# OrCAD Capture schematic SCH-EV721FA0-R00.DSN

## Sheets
1 Block Diagram: title: G2; rev: 1.0; note: Ver1.0
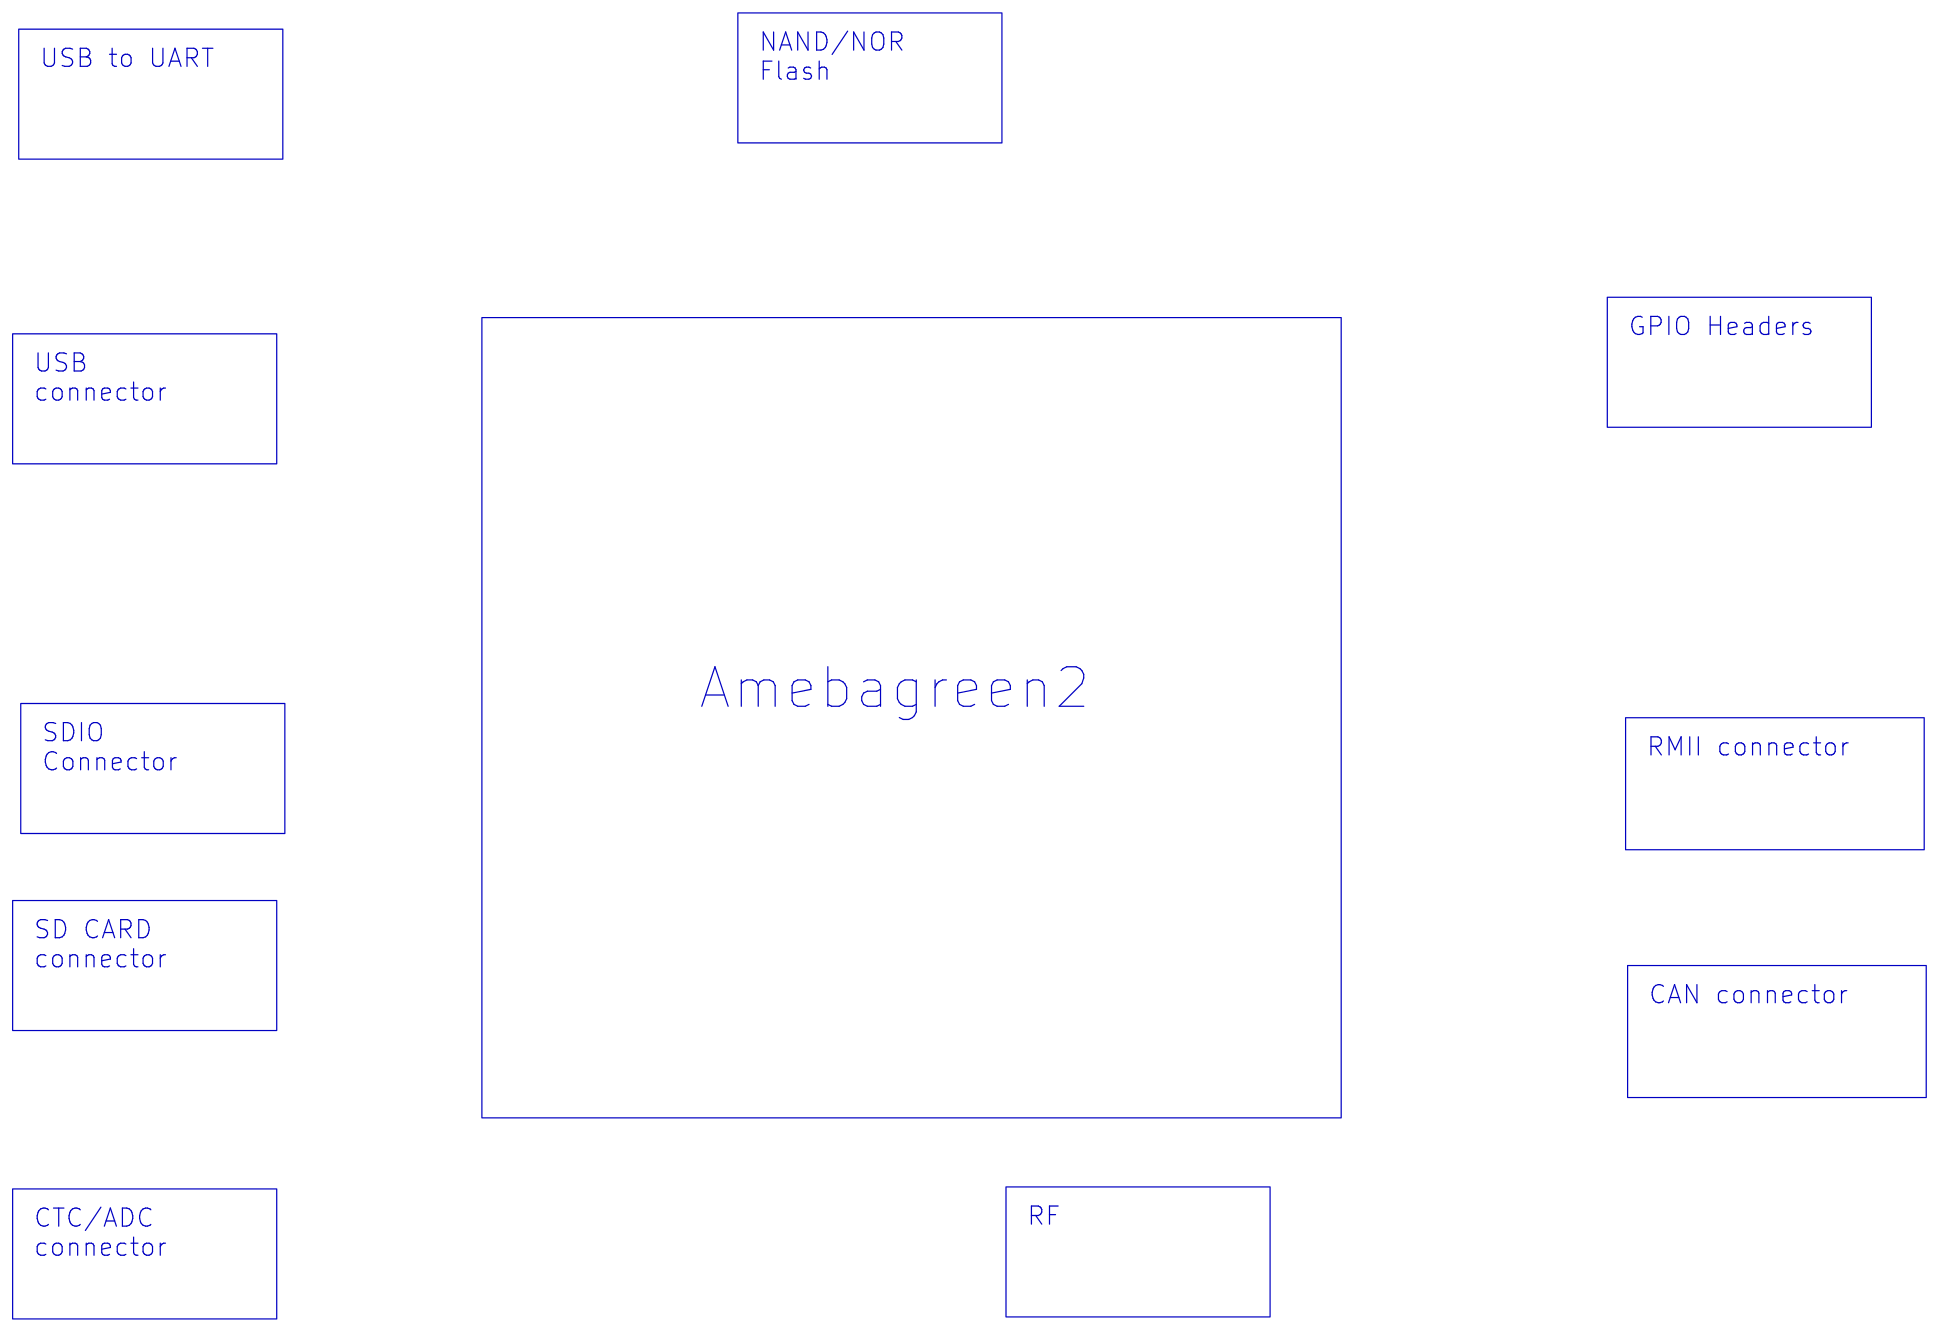
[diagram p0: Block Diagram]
2 Power Tree
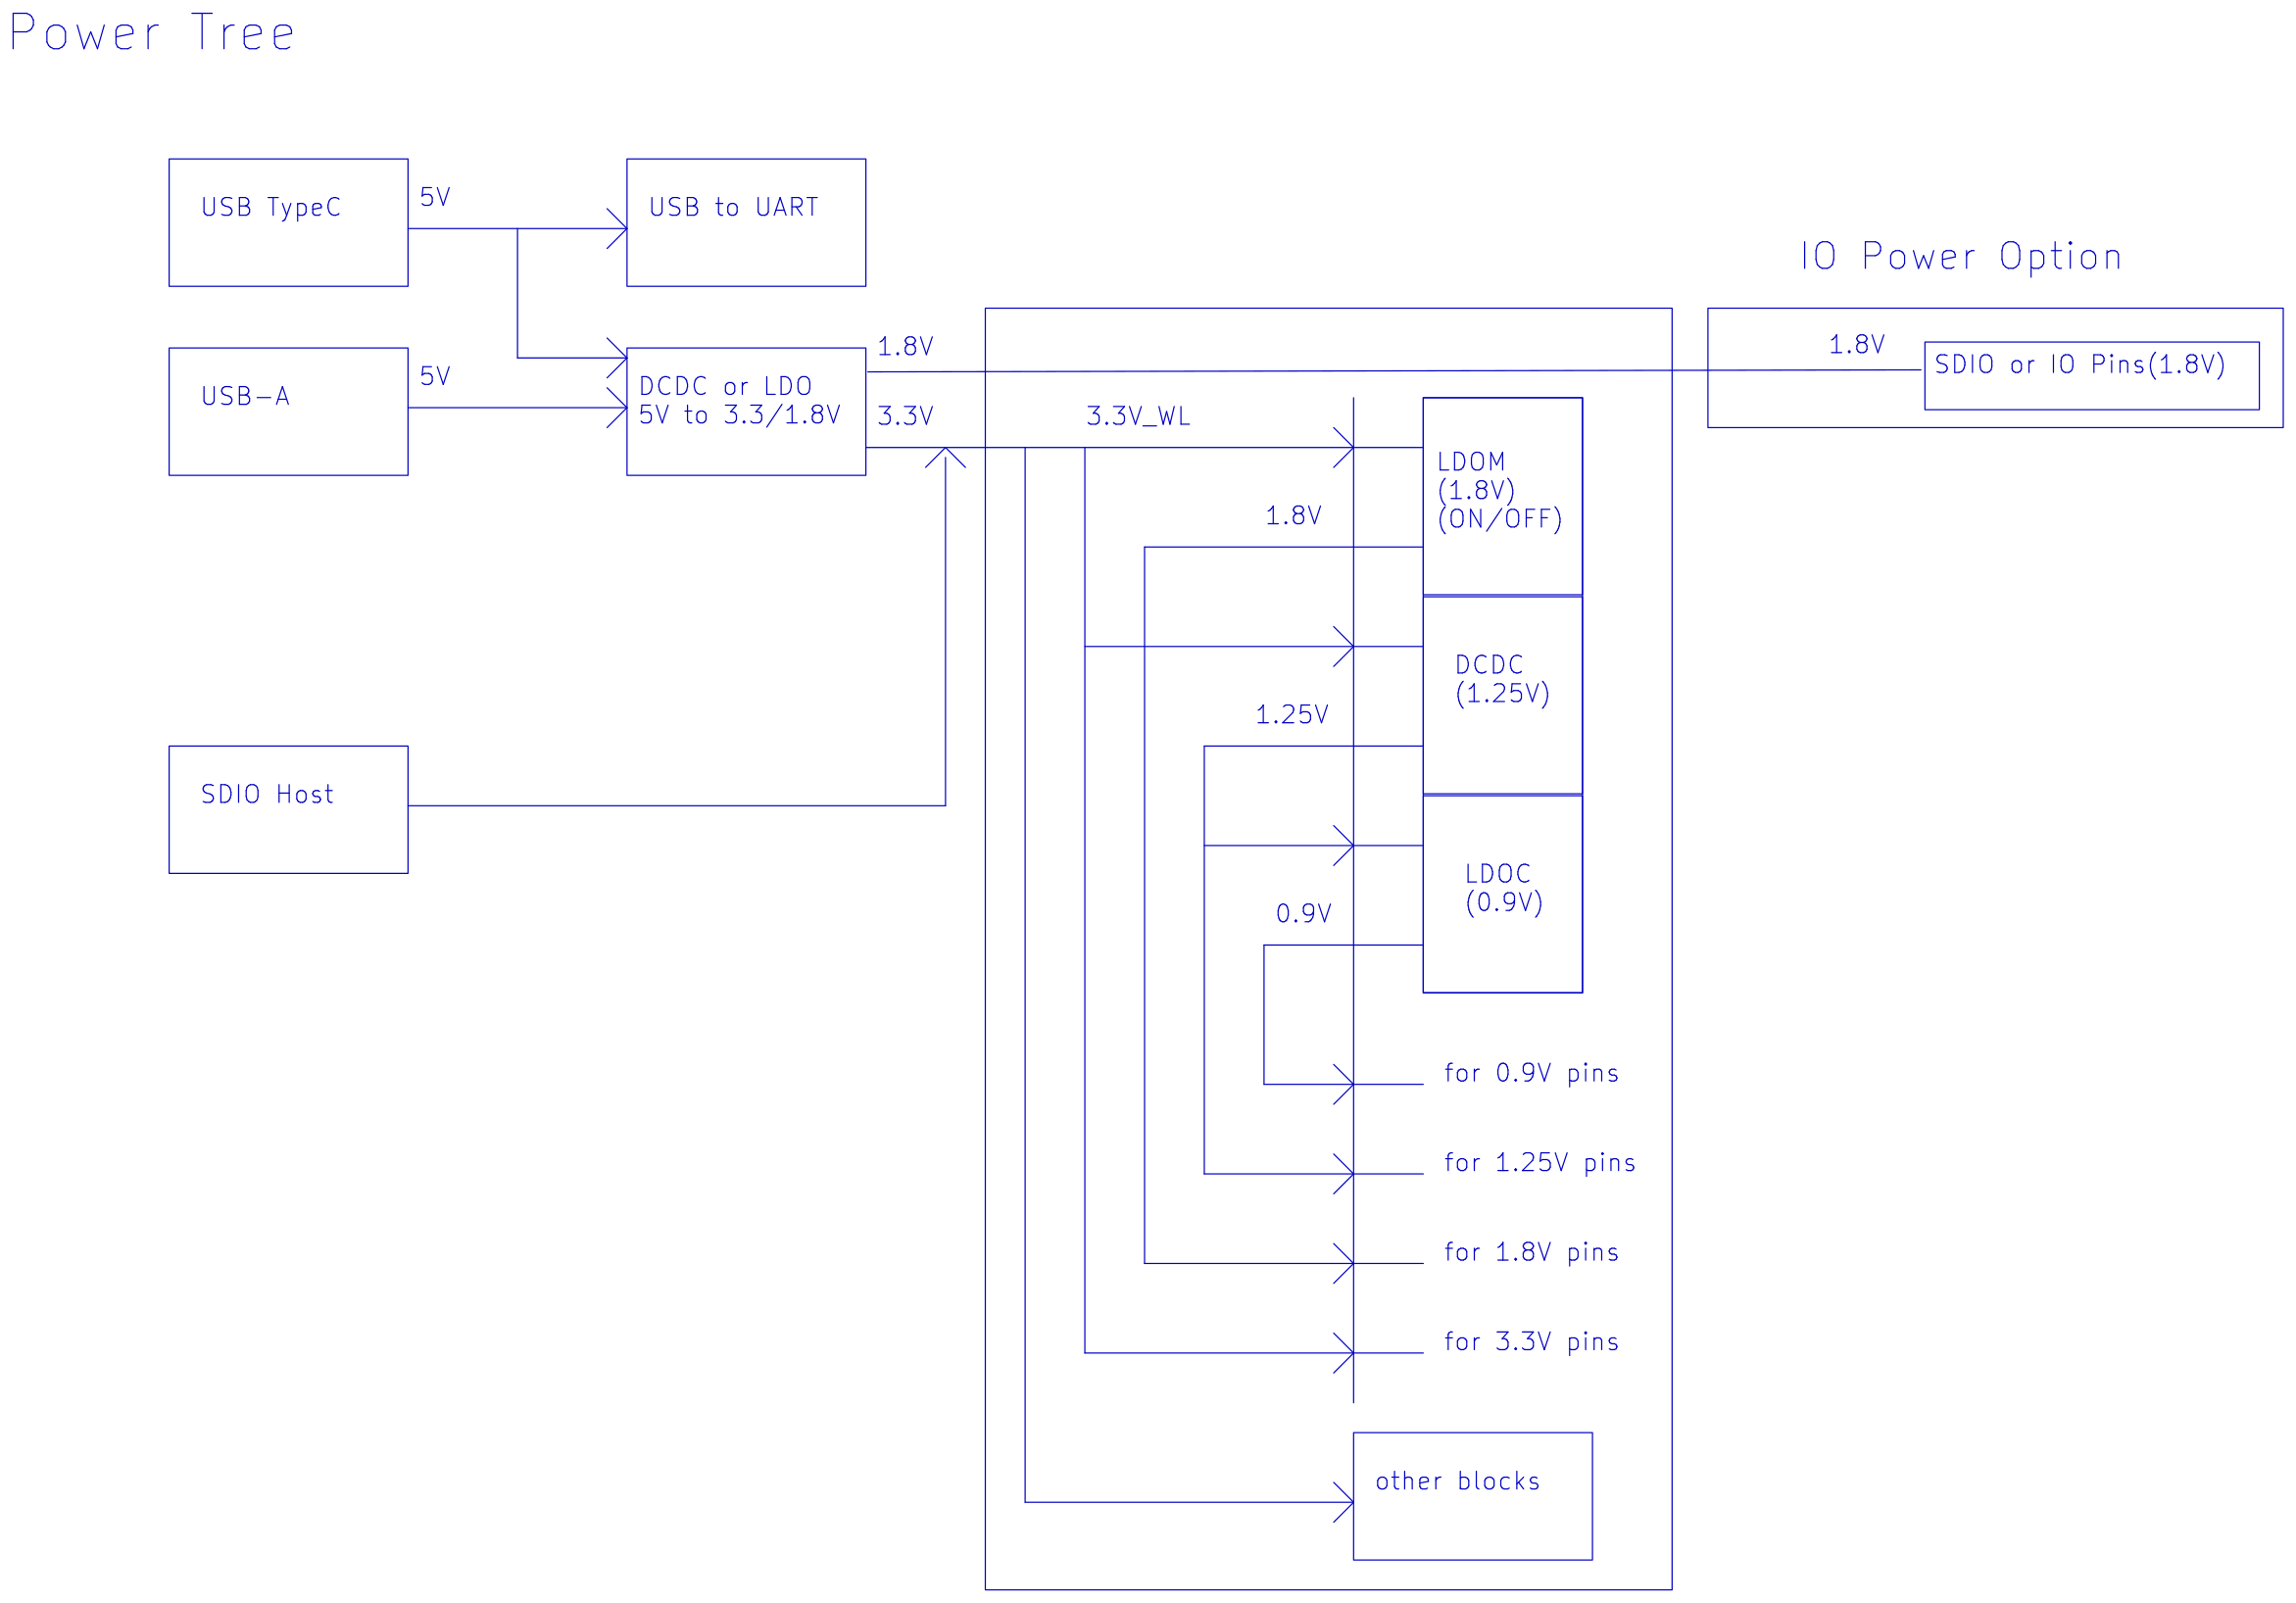
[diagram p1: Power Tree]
3 USB&POWER: size C
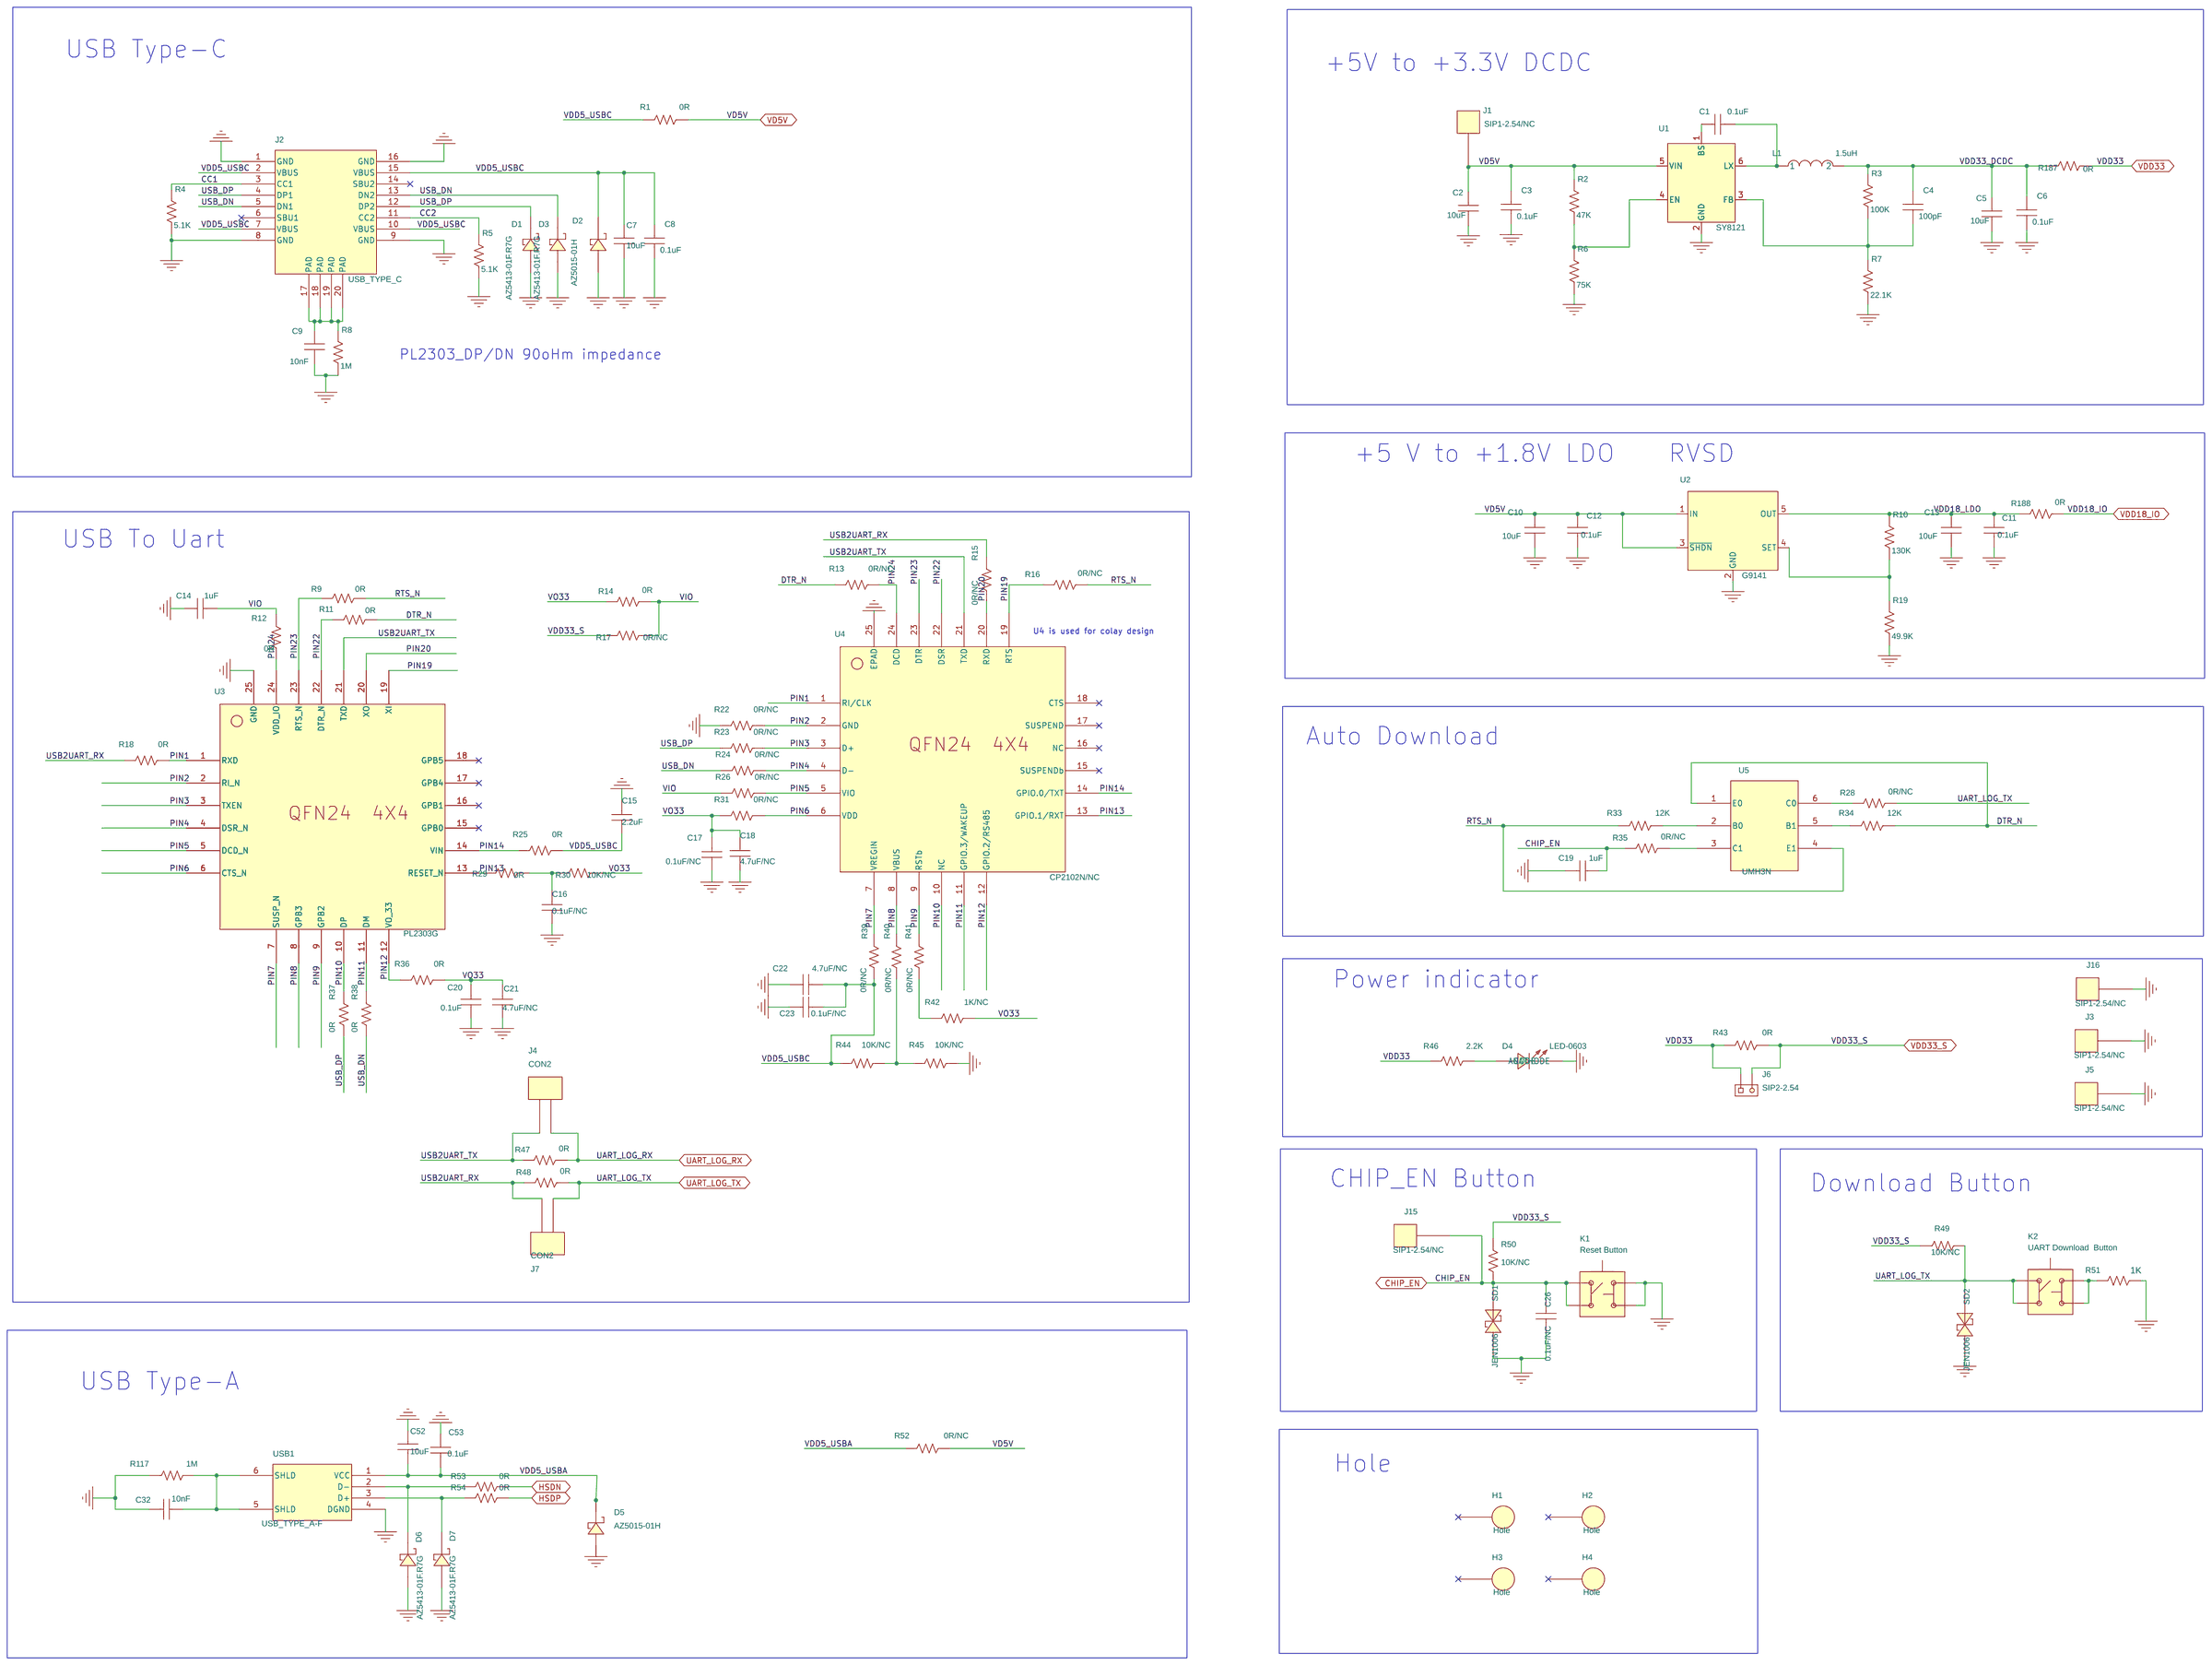
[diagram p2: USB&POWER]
4 Module: size C
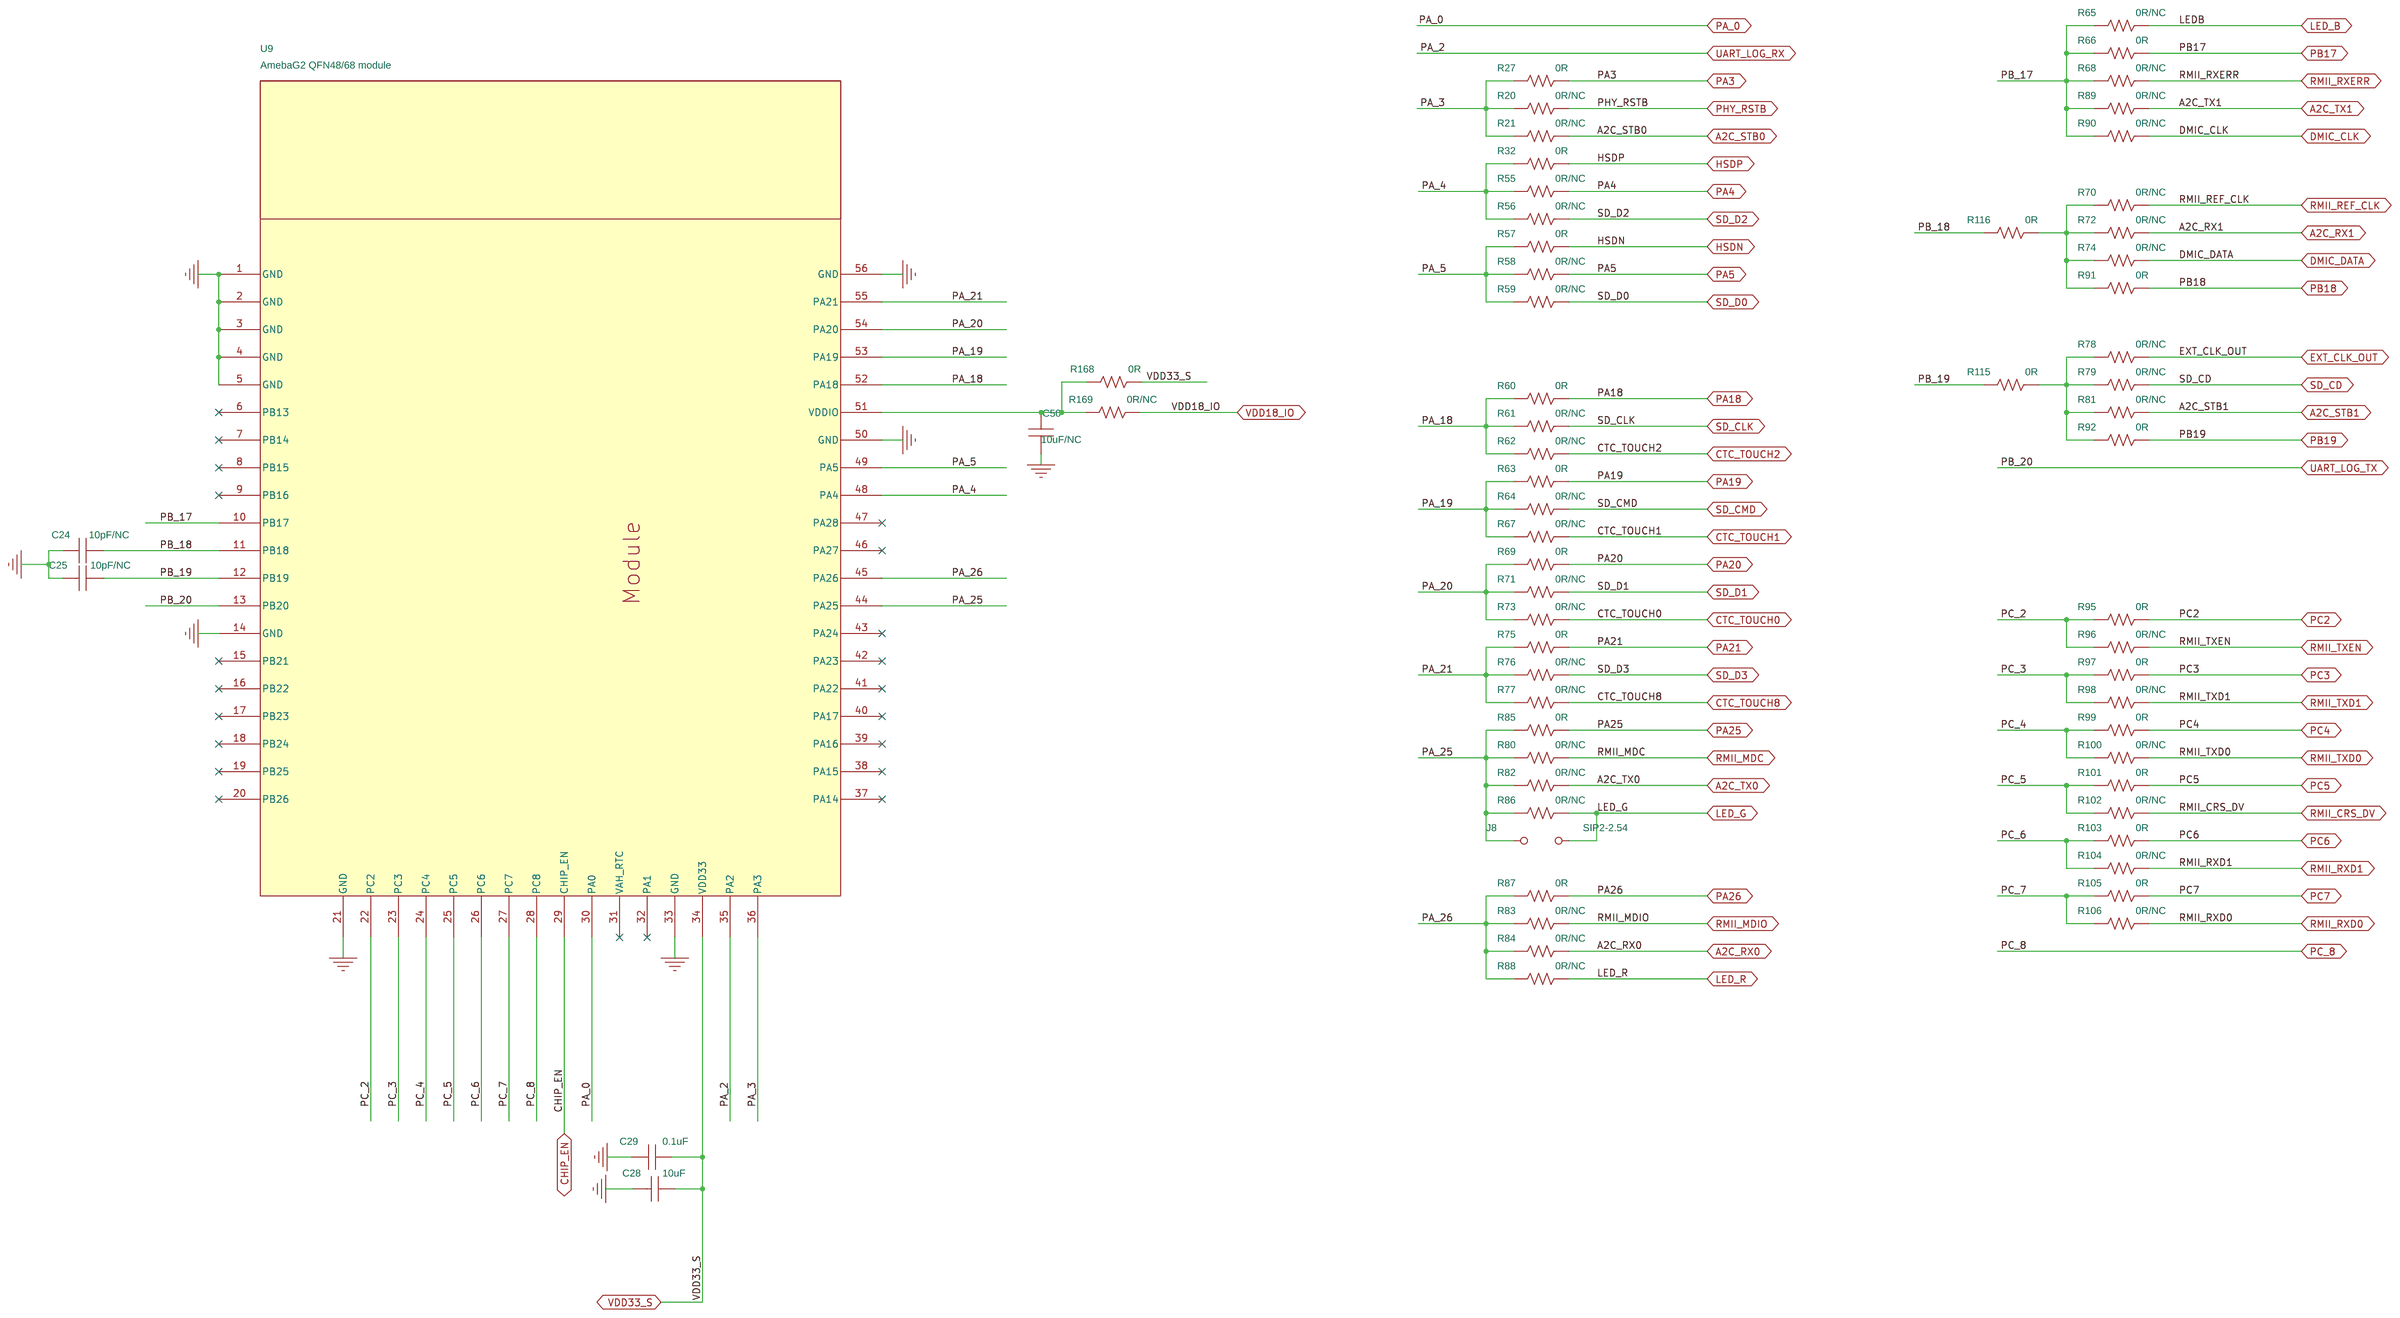
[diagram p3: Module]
5 Function: size C
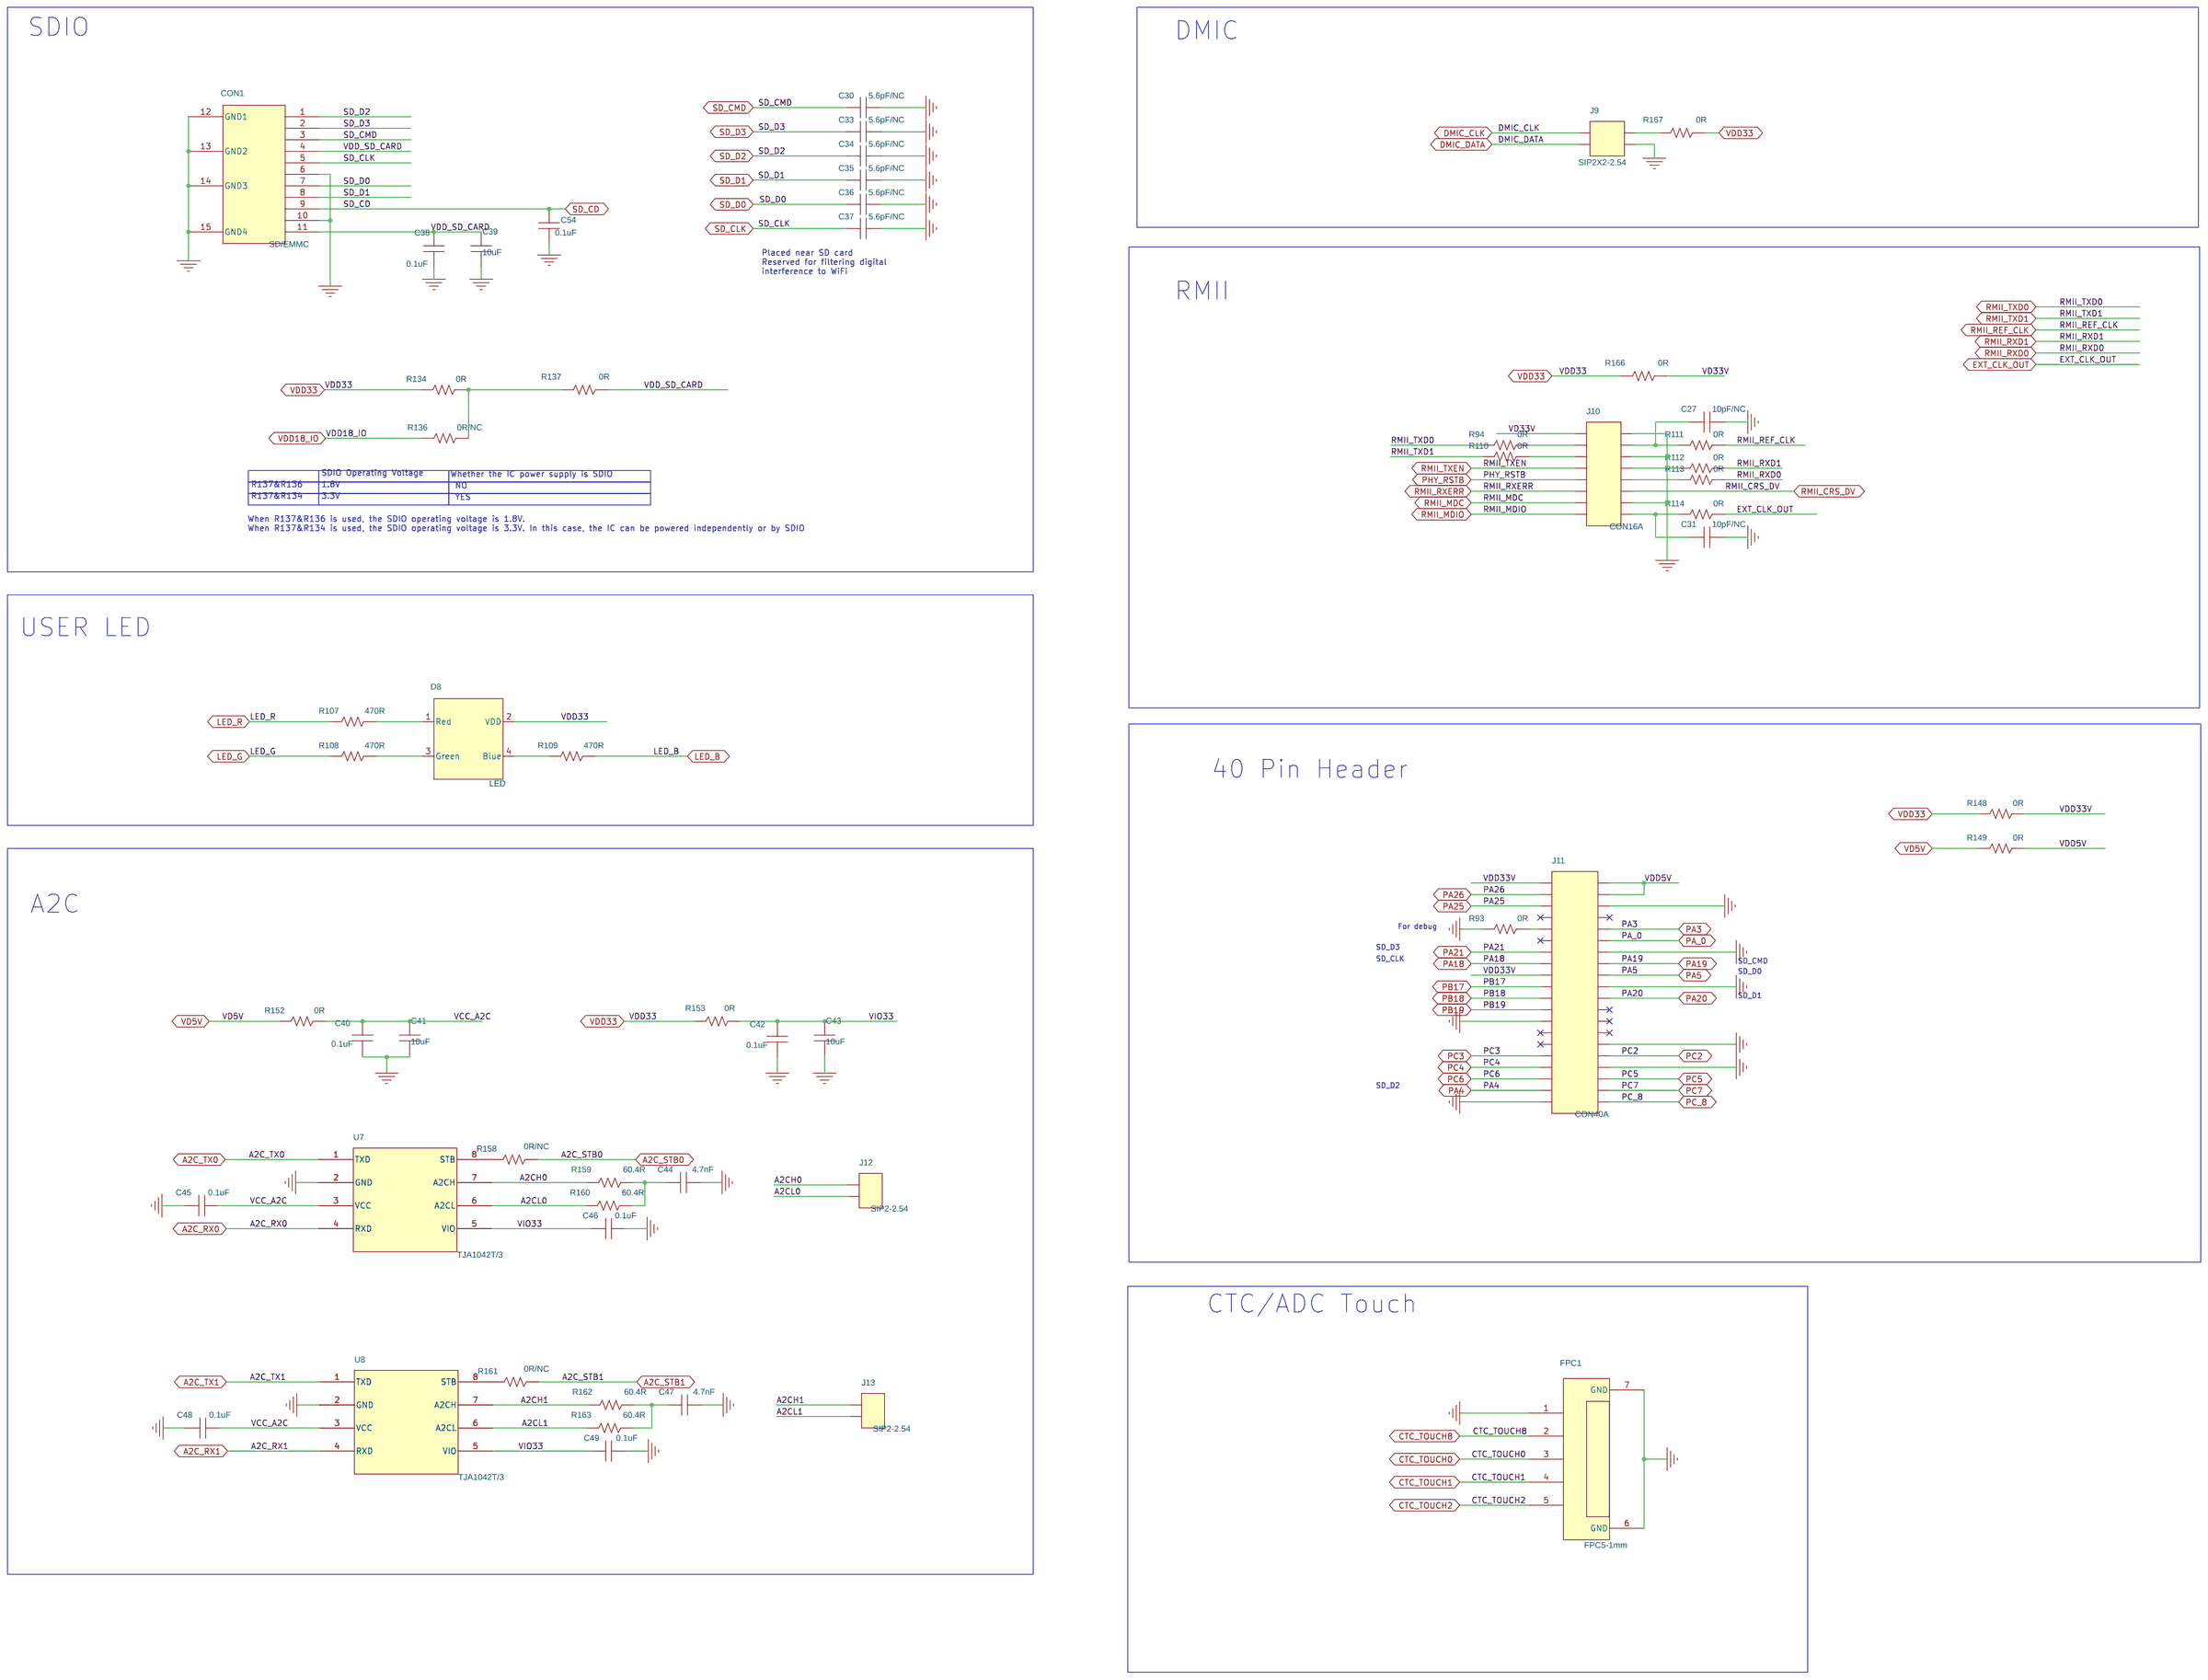
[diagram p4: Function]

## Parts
sheet Function
C27  10pF/NC  [C0402]
C30  5.6pF/NC  [C0402]
C31  10pF/NC  [C0402]
C33  5.6pF/NC  [C0402]
C34  5.6pF/NC  [C0402]
C35  5.6pF/NC  [C0402]
C36  5.6pF/NC  [C0402]
C37  5.6pF/NC  [C0402]
C38  0.1uF  [C0402]
C39  10uF  [C0603]
C40  0.1uF  [C0402]
C41  10uF  [C0603]
C42  0.1uF  [C0402]
C43  10uF  [C0603]
C44  4.7nF  [C0402]
C45  0.1uF  [C0402]
C46  0.1uF  [C0402]
C47  4.7nF  [C0402]
C48  0.1uF  [C0402]
C49  0.1uF  [C0402]
C54  0.1uF  [C0402]
CON1  SD/EMMC  [SD_CARD15]
D8  LED  [LED-3528]
FPC1  FPC5-1mm  [FPC5-1]
J9  SIP2X2-2.54  [SIP2X2-2.54]
J10  CON16A  [SIP8X2-2.54]
J11  CON40A  [SIP20X2-2.54]
J12  SIP2-2.54  [SIP2-2.54]
J13  SIP2-2.54  [SIP2-2.54]
R93  0R  [R0402]
R94  0R  [R0402]
R107  470R  [R0402]
R108  470R  [R0402]
R109  470R  [R0402]
R110  0R  [R0402]
R111  0R  [R0402]
R112  0R  [R0402]
R113  0R  [R0402]
R114  0R  [R0402]
R134  0R  [R0402]
R136  0R/NC  [R0402]
R137  0R  [R0805]
R148  0R  [R0805]
R149  0R  [R0805]
R152  0R  [R0402]
R153  0R  [R0402]
R158  0R/NC  [R0402]
R159  60.4R  [R0402]
R160  60.4R  [R0402]
R161  0R/NC  [R0402]
R162  60.4R  [R0402]
R163  60.4R  [R0402]
R166  0R  [R0402]
R167  0R  [R0402]
U7  TJA1042T/3  [SO8-150-4.9X3.9]
U8  TJA1042T/3  [SO8-150-4.9X3.9]
sheet Module
C24  10pF/NC  [C0402]
C25  10pF/NC  [C0402]
C28  10uF  [C0603]
C29  0.1uF  [C0603]
C50  10uF/NC  [C0402]
J8  SIP2-2.54  [SIP2-2.54]
R20  0R/NC  [R0402]
R21  0R/NC  [R0402]
R27  0R  [R0402]
R32  0R  [R0402]
R55  0R/NC  [R0402]
R56  0R/NC  [R0402]
R57  0R  [R0402]
R58  0R/NC  [R0402]
R59  0R/NC  [R0402]
R60  0R  [R0402]
R61  0R/NC  [R0402]
R62  0R/NC  [R0402]
R63  0R  [R0402]
R64  0R/NC  [R0402]
R65  0R/NC  [R0402]
R66  0R  [R0402]
R67  0R/NC  [R0402]
R68  0R/NC  [R0402]
R69  0R  [R0402]
R70  0R/NC  [R0402]
R71  0R/NC  [R0402]
R72  0R/NC  [R0402]
R73  0R/NC  [R0402]
R74  0R/NC  [R0402]
R75  0R  [R0402]
R76  0R/NC  [R0402]
R77  0R/NC  [R0402]
R78  0R/NC  [R0402]
R79  0R/NC  [R0402]
R80  0R/NC  [R0402]
R81  0R/NC  [R0402]
R82  0R/NC  [R0402]
R83  0R/NC  [R0402]
R84  0R/NC  [R0402]
R85  0R  [R0402]
R86  0R/NC  [R0402]
R87  0R  [R0402]
R88  0R/NC  [R0402]
R89  0R/NC  [R0402]
R90  0R/NC  [R0402]
R91  0R  [R0402]
R92  0R  [R0402]
R95  0R  [R0402]
R96  0R/NC  [R0402]
R97  0R  [R0402]
R98  0R/NC  [R0402]
R99  0R  [R0402]
R100  0R/NC  [R0402]
R101  0R  [R0402]
R102  0R/NC  [R0402]
R103  0R  [R0402]
R104  0R/NC  [R0402]
R105  0R  [R0402]
R106  0R/NC  [R0402]
R115  0R  [R0402]
R116  0R  [R0402]
R168  0R  [R0402]
R169  0R/NC  [R0402]
U9  AmebaG2 QFN48/68 module  [MODULE56-18X28-PLATEFORM]
sheet USB&POWER
C1  0.1uF  [C0402]
C2  10uF  [C0402]
C3  0.1uF  [C0402]
C4  100pF  [C0402]
C5  10uF  [C0402]
C6  0.1uF  [C0402]
C7  10uF  [C0603]
C8  0.1uF  [C0402]
C9  10nF  [C0402]
C10  10uF  [C0402]
C11  0.1uF  [C0402]
C12  0.1uF  [C0402]
C13  10uF  [C0402]
C14  1uF  [C0402]
C15  2.2uF  [C0402]
C16  0.1uF/NC  [C0402]
C17  0.1uF/NC  [C0402]
C18  4.7uF/NC  [C0402]
C19  1uF  [C0402]
C20  0.1uF  [C0402]
C21  4.7uF/NC  [C0402]
C22  4.7uF/NC  [C0402]
C23  0.1uF/NC  [C0402]
C26  0.1uF/NC  [C0402]
C32  10nF  [C0402]
C52  10uF  [C0603]
C53  0.1uF  [C0402]
D1  AZ5413-01F.R7G  [D0402-AZ5413]
D2  AZ5015-01H  [SOD-523]
D3  AZ5413-01F.R7G  [D0402-AZ5413]
D4  LED-0603  [LED-0603]
D5  AZ5015-01H  [SOD-523]
D6  AZ5413-01F.R7G  [D0402-AZ5413]
D7  AZ5413-01F.R7G  [D0402-AZ5413]
H1  Hole  [HOLE-2.7X6.0-NPTH]
H2  Hole  [HOLE-2.7X6.0-NPTH]
H3  Hole  [HOLE-2.7X6.0-NPTH]
H4  Hole  [HOLE-2.7X6.0-NPTH]
J1  SIP1-2.54/NC  [SIP1-2.54]
J2  USB_TYPE_C  [USB-TYPEC-12P-SMD]
J3  SIP1-2.54/NC  [SIP1-2.54]
J4  CON2  [SIP2-2.54]
J5  SIP1-2.54/NC  [SIP1-2.54]
J6  SIP2-2.54  [SIP2-2.54]
J7  CON2  [SIP2-2.54]
J15  SIP1-2.54/NC  [SIP1-2.54]
J16  SIP1-2.54/NC  [SIP1-2.54]
K1  Reset Button  [SW-4P-3X4]
K2  UART Download  Button  [SW-4P-3X4]
L1  1.5uH  [L4442]
R1  0R  [R0805]
R2  47K  [R0402]
R3  100K  [R0402]
R4  5.1K  [R0402]
R5  5.1K  [R0402]
R6  75K  [R0402]
R7  22.1K  [R0402]
R8  1M  [R0402]
R9  0R  [R0201]
R10  130K  [R0402]
R11  0R  [R0201]
R12  0R  [R0201]
R13  0R/NC  [R0201]
R14  0R  [R0402]
R15  0R/NC  [R0201]
R16  0R/NC  [R0201]
R17  0R/NC  [R0402]
R18  0R  [R0201]
R19  49.9K  [R0402]
R22  0R/NC  [R0201]
R23  0R/NC  [R0201]
R24  0R/NC  [R0201]
R25  0R  [R0201]
R26  0R/NC  [R0201]
R28  0R/NC  [R0402]
R29  0R  [R0201]
R30  10K/NC  [R0402]
R31  0R/NC  [R0201]
R33  12K  [R0402]
R34  12K  [R0402]
R35  0R/NC  [R0402]
R36  0R  [R0201]
R37  0R  [R0201]
R38  0R  [R0201]
R39  0R/NC  [R0201]
R40  0R/NC  [R0201]
R41  0R/NC  [R0201]
R42  1K/NC  [R0402]
R43  0R  [R0805]
R44  10K/NC  [R0402]
R45  10K/NC  [R0402]
R46  2.2K  [R0402]
R47  0R  [R0402]
R48  0R  [R0402]
R49  10K/NC  [R0402]
R50  10K/NC  [R0402]
R51  1K  [R0402]
R52  0R/NC  [R0805]
R53  0R  [R0402]
R54  0R  [R0402]
R117  1M  [R0402]
R187  0R  [R0805]
R188  0R  [R0402]
SD1  JEN1006  [D0402-JEN]
SD2  JEN1006  [D0402-JEN]
U1  SY8121  [SOT-23-6]
U2  G9141  [SOT-23-5]
U3  PL2303G  [UQFN24-0.5-4X4-EP1.5X1.5]
U4  CP2102N/NC  [UQFN24-0.5-4X4-EP1.5X1.5]
U5  UMH3N  [SOT-363-1.6]
USB1  USB_TYPE_A-F  [USB-TYPEA-4P-F]

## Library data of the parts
C24 C25 C27 C31 = CAPACITOR_NON-POL_0: ±5%,50V,NPO; Manufacturer: WALSIN; Part Number: 0402N100J500CT; Voltage: 50V; Datasheet: \\172.29.17.1\cn\WLAN\WLAN2\boarddesignLIB\52_component_database\Datasheet\Capacitor\Capacitor_Walsin_MLCC.pdf
C30 C33-C37 = CAPACITOR_NON-POL_0: Part Number: RF15N5R6B500CT; Voltage: 50V; Datasheet: \\172.29.17.1\cn\WLAN\WLAN2\boarddesignLIB\165_component_database\Datasheet\Capacitor\Capacitor_Walsin_MLCC.pdf
C1 C3 C6 C8 C11 C12 C20 C26 C38 C40 C42 C45 C46 C48 C49 C53 C54 = CAPACITOR_NON-POL_0: ±10%,25V,X7R; Manufacturer: WALSIN; Part Number: 0402B104K250CT; Voltage: 25V; Datasheet: \\172.29.17.1\cn\WLAN\WLAN2\boarddesignLIB\06_component_database\Datasheet\Capacitor\Capacitor_Walsin_MLCC.pdf
C7 C28 C39 C41 C43 C52 = CAPACITOR_NON-POL_0: Part Number: 0603X106K250CT; Part Type: Ceramic; Tolerance,Voltage,Dielectric,Lead Free(Y/N): ±10%,25V,X5R; Datasheet: \\172.29.17.1\cn\WLAN\WLAN2\boarddesignLIB\55_component_database\Datasheet\Capacitor\Capacitor_Walsin_MLCC.pdf
C44 C47 = CAPACITOR_NON-POL_0: ±10%,50V,X7R; Manufacturer: WALSIN; Part Number: 0402B472K500CT; Voltage: 50V; Datasheet: \\172.29.17.1\cn\WLAN\WLAN2\boarddesignLIB\144_component_database\Datasheet\Capacitor\Capacitor_Walsin_MLCC.pdf
CON1 = SD-TF21: SD Connector 15PIN; Part Number: SD-TF21-406-S157
D8 = LED_1: 3528雾状全彩RGB,0.1V分光; Manufacturer: Inbright; Part Number: S3528EHMRGBTP-H5-D; Datasheet: \\172.29.17.1\cn\WLAN\WLAN2\boarddesignLIB\01_component_database\Datasheet\Optocoupler-LED-Photoelectric Device\LED_Inbright_S3528EHMRGBTP-H5-D 3528RGB.pdf
FPC1 = FPC-5: 1．0mm-5P.下接翻盖
J9 = CON4A: Pin Header
J10 = CON16A
J11 = CON40A
J12 J13 = CON2: Pin Header
R20 R21 R27 R32 R53-R106 R110-R116 R134 R136 R152 R153 R158 R161 R168 R169 = RES_0: Part Number: WR04X000PTL; Part type: Chip Resistor; Tolerance,Voltage,Dielectric,Lead Free(Y/N): JUMPER; Datasheet: \\172.29.17.1\cn\WLAN\WLAN2\boarddesignLIB\63_component_database\Datasheet\ResistorResistor_Walsin_chipR.pdf
R107-R109 = RES_0: +/-5%; Manufacturer: WALSIN; Part Number: WR04X471 JTL; Datasheet: \\172.29.17.1\cn\WLAN\WLAN2\boarddesignLIB\01_component_database\Datasheet\Resistor\Resistor_Walsin_chipR.pdf
R1 R137 = RES_0: JUMPER; Manufacturer: WALSIN; Part Number: WR08X000PTL; Datasheet: \\172.29.17.1\cn\WLAN\WLAN2\boarddesignLIB\01_component_database\Datasheet\Resistor\Resistor_Walsin_chipR.pdf
R43 R52 R148 R149 R187 = RES_0: Part Number: WR08X000PTL; Part type: Chip Resistor; Tolerance,Voltage,Dielectric,Lead Free(Y/N): JUMPER; Datasheet: \\172.29.17.1\cn\WLAN\WLAN2\boarddesignLIB\65_component_database\Datasheet\ResistorResistor_Walsin_chipR.pdf
R159 R160 R162 R163 = RES_0: +/-1%; Manufacturer: WALSIN; Part Number: WR04X60R4FTL; Datasheet: \\172.29.17.1\cn\WLAN\WLAN2\boarddesignLIB\01_component_database\Datasheet\Resistor\Resistor_Walsin_chipR.pdf
R166 R167 = RES_0: JUMPER; Manufacturer: WALSIN; Part Number: WR04X000PTL; Datasheet: \\172.29.17.1\cn\WLAN\WLAN2\boarddesignLIB\01_component_database\Datasheet\Resistor\Resistor_Walsin_chipR.pdf
U7 U8 = CAN_trans_0: ±8Kv; Datasheet: \\172.29.17.1\cn\WLAN\WLAN2\boarddesignLIB\01_component_database\Datasheet\Communicaton Interface Chip\CAN transceiver_NXP_TJA1042T3.pdf
C29 = CAPACITOR_NON-POL_0: ±10%,25V,X7R,; Manufacturer: WALSIN; Part Number: 0603B104K250CT; Voltage: 25V; Datasheet: \\172.29.17.1\cn\WLAN\WLAN2\boarddesignLIB\07_component_database\Datasheet\Capacitor\Capacitor_Walsin_MLCC.pdf
C2 C5 C10 C13 C50 = CAPACITOR_NON-POL_0: ±10%,16V,X5R; Manufacturer: WALSIN; Part Number: 0402X106K160CT; Voltage: 16V; Datasheet: \\172.29.17.1\cn\WLAN\WLAN2\boarddesignLIB\54_component_database\Datasheet\Capacitor\Capacitor_Walsin_MLCC.pdf
J8 = CON2A: Small symbol，Pin Header
U9 = Amebagreen2_Module_2
C4 = CAPACITOR_NON-POL_0: ±5%,50V,NPO; Manufacturer: WALSIN; Part Number: 0402N101J500CT; Voltage: 50V; Datasheet: \\172.29.17.1\cn\WLAN\WLAN2\boarddesignLIB\47_component_database\Datasheet\Capacitor\Capacitor_Walsin_MLCC.pdf
C9 = CAPACITOR_NON-POL_0: Part Number: 0402B103K250CT; Part Type: Ceramic; Tolerance,Voltage,Dielectric,Lead Free(Y/N): ±10%,25V,X7R; Datasheet: \\172.29.17.1\cn\WLAN\WLAN2\boarddesignLIB\50_component_database\Datasheet\Capacitor\Capacitor_Walsin_MLCC.pdf
C14 = CAPACITOR_NON-POL_0: Part Number: 0402X105K250CT; Part Type: Ceramic; Tolerance,Voltage,Dielectric,Lead Free(Y/N): ±10%,25V,X5R; Datasheet: \\172.29.17.1\cn\WLAN\WLAN2\boarddesignLIB\84_component_database\Datasheet\Capacitor\Capacitor_Walsin_MLCC.pdf
C15 = CAPACITOR_NON-POL_0: Part Number: 0402X225K250CT; Part Type: Ceramic; Tolerance,Voltage,Dielectric,Lead Free(Y/N): ±10%,25V,X5R; Datasheet: \\172.29.17.1\cn\WLAN\WLAN2\boarddesignLIB\93_component_database\Datasheet\Capacitor\Capacitor_Walsin_MLCC.pdf
C16 C17 C23 = CAPACITOR_NON-POL_0: Part Number: 0402B104K250CT; Part Type: Ceramic; Tolerance,Voltage,Dielectric,Lead Free(Y/N): ±10%,25V X7R,; Datasheet: \\172.29.17.1\cn\WLAN\WLAN2\boarddesignLIB\06_component_database\Datasheet\Capacitor\Capacitor_Walsin_MLCC.pdf
C18 C22 = CAPACITOR_NON-POL_0: ±20%,16V,X5R; Manufacturer: WALSIN; Part Number: 0402X475M160CT; Voltage: 16V; Datasheet: \\172.29.17.1\cn\WLAN\WLAN2\boarddesignLIB\147_component_database\Datasheet\Capacitor\Capacitor_Walsin_MLCC.pdf
C19 = CAPACITOR_NON-POL_0: ±10%,25V,X5R; Manufacturer: WALSIN; Part Number: 0402X105K250CT; Voltage: 25V; Datasheet: \\172.29.17.1\cn\WLAN\WLAN2\boarddesignLIB\84_component_database\Datasheet\Capacitor\Capacitor_Walsin_MLCC.pdf
C21 = CAPACITOR_NON-POL_0: Part Number: 0402X106M160CT; Part Type: Ceramic; Tolerance,Voltage,Dielectric,Lead Free(Y/N): ±20%,16V,X5R; Datasheet: \\172.29.17.1\cn\WLAN\WLAN2\boarddesignLIB\54_component_database\Datasheet\Capacitor\Capacitor_Walsin_MLCC.pdf
C32 = CAPACITOR_NON-POL_0: ±10%,25V,X7R; Manufacturer: WALSIN; Part Number: 0402B103K250CT; Voltage: 25V; Datasheet: \\172.29.17.1\cn\WLAN\WLAN2\boarddesignLIB\50_component_database\Datasheet\Capacitor\Capacitor_Walsin_MLCC.pdf
D1 D3 = Uni-directional_ESD_0: Uni-directional, 3.6V; Part Number: AZ5413-01F; Datasheet: \\172.29.17.1\cn\WLAN\WLAN2\boarddesignLIB\01_component_database\Datasheet\TVS\TVS_Amazing_AZ5413-01F.pdf
D2 = Uni-directional_ESD_0: Uni-directional, 6V; Datasheet: \\172.29.17.1\cn\WLAN\WLAN2\boarddesignLIB\01_component_database\Datasheet\TVS\TVS_Amazing_AZ5015-01H.pdf
D4 = LED_0: SMT LED; Part Type: LED
D5 = Uni-directional_ESD_0: Uni-directional, 6V; Part Type: ESD; Datasheet: \\172.29.17.1\cn\WLAN\WLAN2\boarddesignLIB\01_component_database\Datasheet\TVS\TVS_Amazing_AZ5015-01H.pdf
D6 D7 = Uni-directional_ESD_0: Uni-directional, 3.6V; Manufacturer: Amazing; Part Number: AZ5413-01F; Datasheet: \\172.29.17.1\cn\WLAN\WLAN2\boarddesignLIB\01_component_database\Datasheet\TVS\TVS_Amazing_AZ5413-01F.pdf
H1-H4 = HOLE_0: Hole NPTH
J1 J3 J5 J15 J16 = CON1: Pin Header; Part Type: Pin Header
J2 = USB_TYPE_C_0: TYPE C 16 PIN TOP MOUNT SMT; Manufacturer: Molex; Part Number: 2171790001; Datasheet: \\172.29.17.1\cn\WLAN\WLAN2\boarddesignLIB\01_component_database\Datasheet\Connector\Type-C_Molex_2171790001_sd.pdf
J4 J7 = CON2_v2
J6 = HEADER2_0: Pin Header; Part Type: Pin Header
K1 K2 = BUTTON_0: Part Number: TSA343G00-250DZY
L1 = INDUCTOR_POWER: Part Number: MWSA0402-1R5MT; Part Type: Power Inductor; Õ`²îÖµTolerance(nH/%),Q‚Ž(min): 3A,±20%
R2 = RES_0: +/-5%; Manufacturer: WALSIN; Part Number: WR04X473 JTL; Datasheet: \\172.29.17.1\cn\WLAN\WLAN2\boarddesignLIB\01_component_database\Datasheet\Resistor\Resistor_Walsin_chipR.pdf
R3 = RES_0: +/-5%; Manufacturer: WALSIN; Part Number: WR04X104JTL; Datasheet: \\172.29.17.1\cn\WLAN\WLAN2\boarddesignLIB\01_component_database\Datasheet\Resistor\Resistor_Walsin_chipR.pdf
R4 R5 = RES_0: Part Number: WR04X5101FTL; Tolerance,Voltage,Dielectric,Lead Free(Y/N): +/-1%; Datasheet: \\172.29.17.1\cn\WLAN\WLAN2\boarddesignLIB\180_component_database\Datasheet\Resistor\Resistor_Walsin_chipR.pdf
R6 = RES_0: +/-1%; Manufacturer: WALSIN; Part Number: WR04X7502FTL; Datasheet: \\172.29.17.1\cn\WLAN\WLAN2\boarddesignLIB\01_component_database\Datasheet\Resistor\Resistor_Walsin_chipR.pdf
R7 = RES_0: +/-1%; Manufacturer: WALSIN; Part Number: WR04X2212FTL; Datasheet: \\172.29.17.1\cn\WLAN\WLAN2\boarddesignLIB\01_component_database\Datasheet\Resistor\Resistor_Walsin_chipR.pdf
R8 = RES_0: Part Number: WR04X1004FTL; Tolerance,Voltage,Dielectric,Lead Free(Y/N): +/-1%; Datasheet: \\172.29.17.1\cn\WLAN\WLAN2\boarddesignLIB\252_component_database\Datasheet\Resistor\Resistor_Walsin_chipR.pdf
R9 R11-R13 R15 R16 R18 R22-R26 R29 R31 R36-R41 = RES_0: JUMPER; Manufacturer: WALSIN; Part Number: WR02X000PTL; Datasheet: \\172.29.17.1\cn\WLAN\WLAN2\boarddesignLIB\01_component_database\Datasheet\Resistor\Resistor_Walsin_chipR.pdf
R10 = RES_0: +/-5%; Manufacturer: WALSIN; Part Number: WR04X134 JTL; Datasheet: \\172.29.17.1\cn\WLAN\WLAN2\boarddesignLIB\01_component_database\Datasheet\Resistor\Resistor_Walsin_chipR.pdf
R14 R17 R28 R35 R47 R48 R188 = RES_0: Part Number: WR04X000PTL; Tolerance,Voltage,Dielectric,Lead Free(Y/N): JUMPER; Datasheet: \\172.29.17.1\cn\WLAN\WLAN2\boarddesignLIB\64_component_database\Datasheet\Resistor\Resistor_Walsin_chipR.pdf
R19 = RES_0: +/-1%; Manufacturer: WALSIN; Part Number: WR04X4992FTL; Datasheet: \\172.29.17.1\cn\WLAN\WLAN2\boarddesignLIB\01_component_database\Datasheet\Resistor\Resistor_Walsin_chipR.pdf
R30 R44 R45 = RES_0: Part Number: WR04X1002 FTL; Part type: Chip Resistor; Tolerance,Voltage,Dielectric,Lead Free(Y/N): +/-1%; Datasheet: \\172.29.17.1\cn\WLAN\WLAN2\boarddesignLIB\190_component_database\Datasheet\ResistorResistor_Walsin_chipR.pdf
R33 R34 = RES_0: +/-5%; Manufacturer: WALSIN; Part Number: WR04X123 JTL; Datasheet: \\172.29.17.1\cn\WLAN\WLAN2\boarddesignLIB\01_component_database\Datasheet\Resistor\Resistor_Walsin_chipR.pdf
R42 = RES_0: +/-1%; Manufacturer: WALSIN; Part Number: WR04X1001FTL; Datasheet: \\172.29.17.1\cn\WLAN\WLAN2\boarddesignLIB\01_component_database\Datasheet\Resistor\Resistor_Walsin_chipR.pdf
R46 = RES_0: Part Number: WR04X222 JTL; Part type: Chip Resistor; Tolerance,Voltage,Dielectric,Lead Free(Y/N): +/-5%; Datasheet: \\172.29.17.1\cn\WLAN\WLAN2\boarddesignLIB\164_component_database\Datasheet\ResistorResistor_Walsin, chipR.pdf
R49 R50 = RES_0: Part Number: WR04X1002 FTL; Tolerance,Voltage,Dielectric,Lead Free(Y/N): +/-1%; Datasheet: \\172.29.17.1\cn\WLAN\WLAN2\boarddesignLIB\191_component_database\Datasheet\Resistor\Resistor_Walsin_chipR.pdf
R51 = RES_V: +/-1%; Manufacturer: WALSIN; Part Number: WR04X1003FTL; Unit Price(USD): 0.00032; Datasheet: \\172.29.17.1\cn\WLAN\WLAN2\boarddesignLIB\01_component_database\Datasheet\Resistor\Resistor_Walsin_chipR.pdf
R117 = RES_0: +/-1%; Manufacturer: WALSIN; Part Number: WR04X1004FTL; Datasheet: \\172.29.17.1\cn\WLAN\WLAN2\boarddesignLIB\01_component_database\Datasheet\Resistor\Resistor_Walsin_chipR.pdf
SD1 SD2 = Bi-directional_ESD_0: Bi-directional, 3.3V; Manufacturer: JDT Fuse; Part Number: JEN1006-3.3V-ULC; Datasheet: \\172.29.17.1\cn\WLAN\WLAN2\boarddesignLIB\01_component_database\Datasheet\TVS\TVS_JDTfuse_JEN1006-3.3V-ULC.pdf
U1 = SY8121C1ABC: 2A Load Current, 1.2MHz Switching Freq; Part Type: DCDC; Datasheet: \\172.29.17.1\cn\WLAN\WLAN2\boarddesignLIB\01_component_database\Datasheet\Power Supply ChipDCDC_Silergy, AN_SY8121C1.pdf
U2 = G9141: Dropout Voltage is 800mV @ 600mA Load; Manufacturer: GMT; Part Number: G9141T11U; Datasheet: \\172.29.17.1\cn\WLAN\WLAN2\boarddesignLIB\01_component_database\Datasheet\Power Supply Chip\LDO_GMT_EDS-9141.pdf
U3 = PL2303GC_QFN: USB to RS232,RS422,RS485, 16 GPIO pins can be used; Part Number: PL2303G4FIG7P2; Part Type: USB IC; Datasheet: \\172.29.17.1\cn\WLAN\WLAN2\boarddesignLIB\01_component_database\Datasheet\Communicaton Interface Chip\USB2UART_Prolific_PL2303GC.pdf
U4 = CP2102N_QFN: USB to RS232,RS422,RS485, 16 GPIO pins can be used; Manufacturer: Silicon Labs; Part Number: CP2102N; Datasheet: \\172.29.17.1\cn\WLAN\WLAN2\boarddesignLIB\01_component_database\Datasheet\Communicaton Interface Chip\USB2UART_Silicon Labs_CP2102N-A02-GQFN24R_规格书_WJ339251.pdf
U5 = UMH3N: 2个NPN-预偏置 100mA 50V; Part Type: NPN-BJT; Datasheet: \\172.29.17.1\cn\WLAN\WLAN2\boarddesignLIB\01_component_database\Datasheet\Triode-MOS Tube-Transistor\NPN-BJT_ROHM, UMH3NTN.pdf
USB1 = USB_TYPE_A_F0: TYPE-A母头

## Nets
GND: C2.2 C3.2 C5.2 C6.2 C7.2 C8.2 C9.2 C10.2 C11.2 C12.2 C13.2 C14.1 C15.2 C16.1 C17.1 C18.2 C19.2 C20.1 C21.1 C22.1 C23.1 C24.1 C25.1 C26.2 C27.2 C28.2 C29.2 C30.2 C31.2 C32.2 C33.2 C34.2 C35.2 C36.2 C37.2 C38.2 C39.2 C40.2 C41.2 C42.2 C43.2 C44.2 C45.2 C46.1 C47.2 C48.2 C49.2 C50.2 C52.1 C53.1 C54.2 CON1.6 CON1.10 CON1.12(GND1) CON1.13(GND2) CON1.14(GND3) CON1.15(GND4) D1.2 D2.2 D3.2 D4.2(CATHODE) D5.2 D6.2 D7.2 FPC1.1 FPC1.6(GND) FPC1.7(GND) J2.1(GND) J2.8(GND) J2.9(GND) J2.16(GND) J3.1 J5.1 J9.4 J10.2 J10.6 J10.14 J11.6 J11.14 J11.20 J11.25 J11.30 J11.34 J11.39 J16.1 K1.3 K1.4 R4.2 R5.2 R6.2 R7.2 R8.2 R19.2 R22.1 R45.2 R51.2 R93.1 R117.2 SD1.2 SD2.2 U1.2(GND) U2.2(GND) U3.25(GND) U4.25(EPAD) U7.2(GND) U8.2(GND) U9.1(GND) U9.2(GND) U9.3(GND) U9.4(GND) U9.5(GND) U9.14(GND) U9.21(GND) U9.33(GND) U9.50(GND) U9.56(GND) USB1.4(DGND)
VCC_A2C: C40.1 C41.1 C45.1 C48.1 R152.2 U7.3(VCC) U8.3(VCC)
VDD5_USBA: C52.2 C53.2 D5.1 R52.1 USB1.1(VCC)
VDD5_USBC: C7.1 C8.1 C15.1 C22.2 C23.2 D2.1 J2.2(VBUS) J2.7(VBUS) J2.10(VBUS) J2.15(VBUS) R1.1 R25.2 R39.1 R44.1
VDD5V: J11.2 J11.4 R149.2
VDD18_IO: R136.1 R169.2 R188.2
VDD18_LDO: C11.1 C13.1 R10.1 R188.1 U2.5(OUT)
VDD33: D8.2(VDD) J6.1 R43.1 R46.1 R134.1 R148.1 R153.1 R166.1 R167.2 R187.2
VDD33_DCDC: C4.1 C5.1 C6.1 L1.2 R3.1 R187.1
VDD33_S: C28.1 C29.1 J6.2 R17.1 R43.2 R49.2 R50.2 R168.2 U9.34(VDD33)
VDD33V: J11.1 J11.17 R148.2
VDD_SD_CARD: C38.1 C39.1 CON1.4 CON1.11 R137.2
A2C_RX0: R84.2 U7.4(RXD)
A2C_RX1: R72.2 U8.4(RXD)
A2C_STB0: R21.2 R158.2
A2C_STB1: R81.2 R161.2
A2C_TX0: R82.2 U7.1(TXD)
A2C_TX1: R89.2 U8.1(TXD)
A2CH0: J12.1 R159.1 U7.7(A2CH)
A2CH1: J13.1 R162.1 U8.7(A2CH)
A2CL0: J12.2 R160.1 U7.6(A2CL)
A2CL1: J13.2 R163.1 U8.6(A2CL)
CC1: J2.3(CC1) R4.1
CC2: J2.11(CC2) R5.1
CHIP_EN: C19.1 C26.1 J15.1 K1.1 K1.2 R35.1 R50.1 SD1.1 U9.29(CHIP_EN)
CTC_TOUCH0: FPC1.3 R73.2
CTC_TOUCH1: FPC1.4 R67.2
CTC_TOUCH2: FPC1.5 R62.2
CTC_TOUCH8: FPC1.2 R77.2
DMIC_CLK: J9.1 R90.2
DMIC_DATA: J9.3 R74.2
DTR_N: R11.2 R13.1 R34.2 U5.1(E0)
EXT_CLK_OUT: R78.2 R114.2
HSDN: R53.2 R57.2
HSDP: R32.2 R54.2
LED_B: R65.2 R109.2
LED_G: J8.2 R86.2 R108.1
LED_R: R88.2 R107.1
PA3: J11.10 R27.2
PA4: J11.37 R55.2
PA5: J11.18 R58.2
PA18: J11.15 R60.2
PA19: J11.16 R63.2
PA20: J11.22 R69.2
PA21: J11.13 R75.2
PA25: J11.5 R85.2
PA26: J11.3 R87.2
PA_0: J11.12 U9.30(PA0)
PA_3: R20.1 R21.1 R27.1 U9.36(PA3)
PA_4: R32.1 R55.1 R56.1 U9.48(PA4)
PA_5: R57.1 R58.1 R59.1 U9.49(PA5)
PA_18: R60.1 R61.1 R62.1 U9.52(PA18)
PA_19: R63.1 R64.1 R67.1 U9.53(PA19)
PA_20: R69.1 R71.1 R73.1 U9.54(PA20)
PA_21: R75.1 R76.1 R77.1 U9.55(PA21)
PA_25: J8.1 R80.1 R82.1 R85.1 R86.1 U9.44(PA25)
PA_26: R83.1 R84.1 R87.1 R88.1 U9.45(PA26)
PB17: J11.19 R66.2
PB18: J11.21 R91.2
PB19: J11.23 R92.2
PB_17: R65.1 R66.1 R68.1 R89.1 R90.1 U9.10(PB17)
PB_18: C24.2 R116.1 U9.11(PB18)
PB_19: C25.2 R115.1 U9.12(PB19)
PC2: J11.32 R95.2
PC3: J11.31 R97.2
PC4: J11.33 R99.2
PC5: J11.36 R101.2
PC6: J11.35 R103.2
PC7: J11.38 R105.2
PC_2: R95.1 R96.1 U9.22(PC2)
PC_3: R97.1 R98.1 U9.23(PC3)
PC_4: R99.1 R100.1 U9.24(PC4)
PC_5: R101.1 R102.1 U9.25(PC5)
PC_6: R103.1 R104.1 U9.26(PC6)
PC_7: R105.1 R106.1 U9.27(PC7)
PC_8: J11.40 U9.28(PC8)
PHY_RSTB: J10.9 R20.2
PIN1: R18.2 U3.1(RXD) U4.1(RI/CLK)
PIN2: R22.2 U3.2(RI_N) U4.2(GND)
PIN3: R23.2 U3.3(TXEN) U4.3(D+)
PIN4: R24.2 U3.4(DSR_N) U4.4(D-)
PIN5: R26.2 U3.5(DCD_N) U4.5(VIO)
PIN6: R31.2 U3.6(CTS_N) U4.6(VDD)
PIN7: R39.2 U3.7(SUSP_N) U4.7(VREGIN)
PIN8: R40.2 U3.8(GPB3) U4.8(VBUS)
PIN9: R41.2 U3.9(GPB2) U4.9(RSTb)
PIN10: R37.2 U3.10(DP) U4.10(NC)
PIN11: R38.2 U3.11(DM) U4.11(GPIO.3/WAKEUP)
PIN12: R36.1 U3.12(VO_33) U4.12(GPIO.2/RS485)
PIN13: R29.1 U3.13(RESET_N) U4.13(GPIO.1/RXT)
PIN14: R25.1 U3.14(VIN) U4.14(GPIO.0/TXT)
PIN19: R16.1 U3.19(XI) U4.19(RTS)
PIN20: R15.1 U3.20(XO) U4.20(RXD)
PIN22: R11.1 U3.22(DTR_N) U4.22(DSR)
PIN23: R9.1 U3.23(RTS_N) U4.23(DTR)
PIN24: R12.1 R13.2 U3.24(VDD_IO) U4.24(DCD)
RMII_CRS_DV: J10.12 R102.2
RMII_MDC: J10.13 R80.2
RMII_MDIO: J10.15 R83.2
RMII_REF_CLK: R70.2 R111.2
RMII_RXD0: R106.2 R113.2
RMII_RXD1: R104.2 R112.2
RMII_RXERR: J10.11 R68.2
RMII_TXD0: R94.1 R100.2
RMII_TXD1: R98.2 R110.1
RMII_TXEN: J10.7 R96.2
RTS_N: R9.2 R16.2 R33.1 U5.4(E1)
SD_CD: C54.1 CON1.9 R79.2
SD_CLK: C37.1 CON1.5 R61.2
SD_CMD: C30.1 CON1.3 R64.2
SD_D0: C36.1 CON1.7 R59.2
SD_D1: C35.1 CON1.8 R71.2
SD_D2: C34.1 CON1.1 R56.2
SD_D3: C33.1 CON1.2 R76.2
UART_LOG_RX: J4.2 R47.2 U9.35(PA2)
UART_LOG_TX: J7.2 K2.1 K2.2 R28.2 R48.2 R49.1 SD2.1 U9.13(PB20)
USB2UART_RX: J7.1 R15.2 R18.1 R48.1
USB2UART_TX: J4.1 R47.1 U3.21(TXD) U4.21(TXD)
USB_DN: D3.1 J2.5(DN1) J2.13(DN2) R24.1 R38.1
USB_DP: D1.1 J2.4(DP1) J2.12(DP2) R23.1 R37.1
VD5V: C2.1 C3.1 C10.1 C12.1 J1.1 R1.2 R2.1 R52.2 R149.1 R152.1 U1.5(VIN) U2.1(IN) U2.3(~{SHDN})
VD33V: J10.1 R166.2
VIO: C14.2 R12.2 R14.2 R17.2 R26.1
VIO33: C42.1 C43.1 C46.2 C49.1 R153.2 U7.5(VIO) U8.5(VIO)
VO33: C17.2 C18.1 C20.2 C21.2 R14.1 R30.2 R31.1 R36.2 R42.2
N16805434: R134.2 R136.2 R137.1
N16835121: C1.2 L1.1 U1.6(LX)
N16835434: R28.1 U5.6(C0)
N16835882: C4.2 R3.2 R7.1 U1.3(FB)
N16838649: C9.1 J2.17(PAD) J2.18(PAD) J2.19(PAD) J2.20(PAD) R8.1
N16848242: C44.1 R159.2 R160.2
N16851426: D7.1 R54.1 USB1.3(D+)
N16851428: D6.1 R53.1 USB1.2(D-)
N16854554: C47.1 R162.2 R163.2
N16861548: D4.1(ANODE) R46.2
N16893821: R2.2 R6.1 U1.4(EN)
N16899697: R10.2 R19.1 U2.4(SET)
N16914157: C16.2 R29.2 R30.1
N16914287: R40.1 R44.2 R45.1
N16914321: R41.1 R42.1
N16940861: C50.1 R168.1 R169.1 U9.51(VDDIO)
N16989899: J9.2 R167.1
N17053670: R70.1 R72.1 R74.1 R91.1 R116.2
N17053856: R78.1 R79.1 R81.1 R92.1 R115.2
N17058188: D8.1(Red) R107.2
N17058190: D8.3(Green) R108.2
N17058192: D8.4(Blue) R109.1
N17082106: J11.9 R93.2
N17088923: J10.3 R94.2
N17088950: J10.5 R110.2
N17089045: C27.1 J10.4 R111.1
N17089264: J10.8 R112.1
N17089320: J10.10 R113.1
N17089377: C31.1 J10.16 R114.1
N17094096: R161.1 U8.8(STB)
N17094097: R158.1 U7.8(STB)
N17095989: C32.1 R117.1 USB1.5(SHLD) USB1.6(SHLD)
N19230922: K2.3 K2.4 R51.1
N19317969: C1.1 U1.1(BS)
N19544535: R34.1 U5.5(B1)
N19544537: R33.2 U5.2(B0)
N19758757: R35.2 U5.3(C1)

Not connected (* = marked no-connect by the designer): H1 1*; H2 1*; H3 1*; H4 1*; J2 6(SBU1)* 14(SBU2)*; J11 7* 8* 11* 24* 26* 27* 28* 29*; U3 15(GPB0)* 16(GPB1)* 17(GPB4)* 18(GPB5)*; U4 15(SUSPENDb)* 16(NC)* 17(SUSPEND)* 18(CTS)*; U9 6(PB13)* 7(PB14)* 8(PB15)* 9(PB16)* 15(PB21)* 16(PB22)* 17(PB23)* 18(PB24)* 19(PB25)* 20(PB26)* 31(VAH_RTC)* 32(PA1)* 37(PA14)* 38(PA15)* 39(PA16)* 40(PA17)* 41(PA22)* 42(PA23)* 43(PA24)* 46(PA27)* 47(PA28)*

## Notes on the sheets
sheet 1
- NAND/NOR
  Flash
- USB to UART
- GPIO Headers
- USB
  connector
- Amebagreen2
- SDIO
  Connector
- RMII connector
- SD CARD
  connector
- CAN connector
- CTC/ADC
  connector
- RF
sheet 2
- Power Tree
- USB TypeC
- 5V
- USB to UART
- IO Power Option
- 1.8V
- 1.8V
- 5V
- SDIO or IO Pins(1.8V)
- USB-A
- DCDC or LDO
  5V to 3.3/1.8V
- 3.3V
- 3.3V_WL
- LDOM
  (1.8V)
  (ON/OFF)
- 1.8V
- DCDC
  (1.25V)
- 1.25V
- SDIO Host
- LDOC
  (0.9V)
- 0.9V
- for 0.9V pins
- for 1.25V pins
- for 1.8V pins
- for 3.3V pins
- other blocks
sheet 3
- USB Type-C
- +5V to +3.3V DCDC
- PL2303_DP/DN 90oHm impedance
- +5 V to +1.8V LDO    RVSD
- USB To Uart
- U4 is used for colay design
- Auto Download
- Power indicator
- CHIP_EN Button
- Download Button
- USB Type-A
- Hole
sheet 5
- SDIO
- DMIC
- Placed near SD card
  Reserved for filtering digital
  interference to WiFi
- RMII
- SDIO Operating Voltage
- Whether the IC power supply is SDIO
- R137&R136
- 1.8V
- NO
- R137&R134
- 3.3V
- YES
- When R137&R136 is used, the SDIO operating voltage is 1.8V.
  When R137&R134 is used, the SDIO operating voltage is 3.3V. In this case, the IC can be powered independently or by SDIO
- USER LED
- 40 Pin Header
- A2C
- For debug
- SD_D3
- SD_CLK
- SD_CMD
- SD_D0
- SD_D1
- SD_D2
- CTC/ADC Touch
